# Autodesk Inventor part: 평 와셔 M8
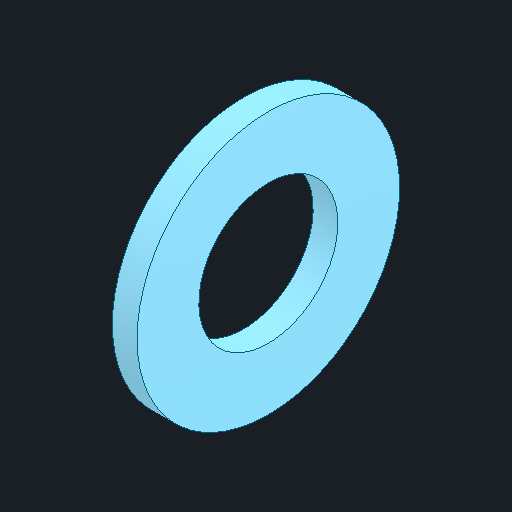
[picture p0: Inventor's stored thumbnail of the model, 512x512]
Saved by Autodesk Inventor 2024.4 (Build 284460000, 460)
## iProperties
Created: 2025-10
Part Number: 평 와셔 M8
Material: 강철, 연강
Description: 평면 와셔
Document SubType Name: Modeling
Designer: user
Density: 7.85 g/cm^3
Appearance: 기본값
Author: jhkim
Sending System: Autodesk Inventor 2026
Preprocessor: ST-DEVELOPER v20.1
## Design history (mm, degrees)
feature "Solid1"
node "솔리드1"
